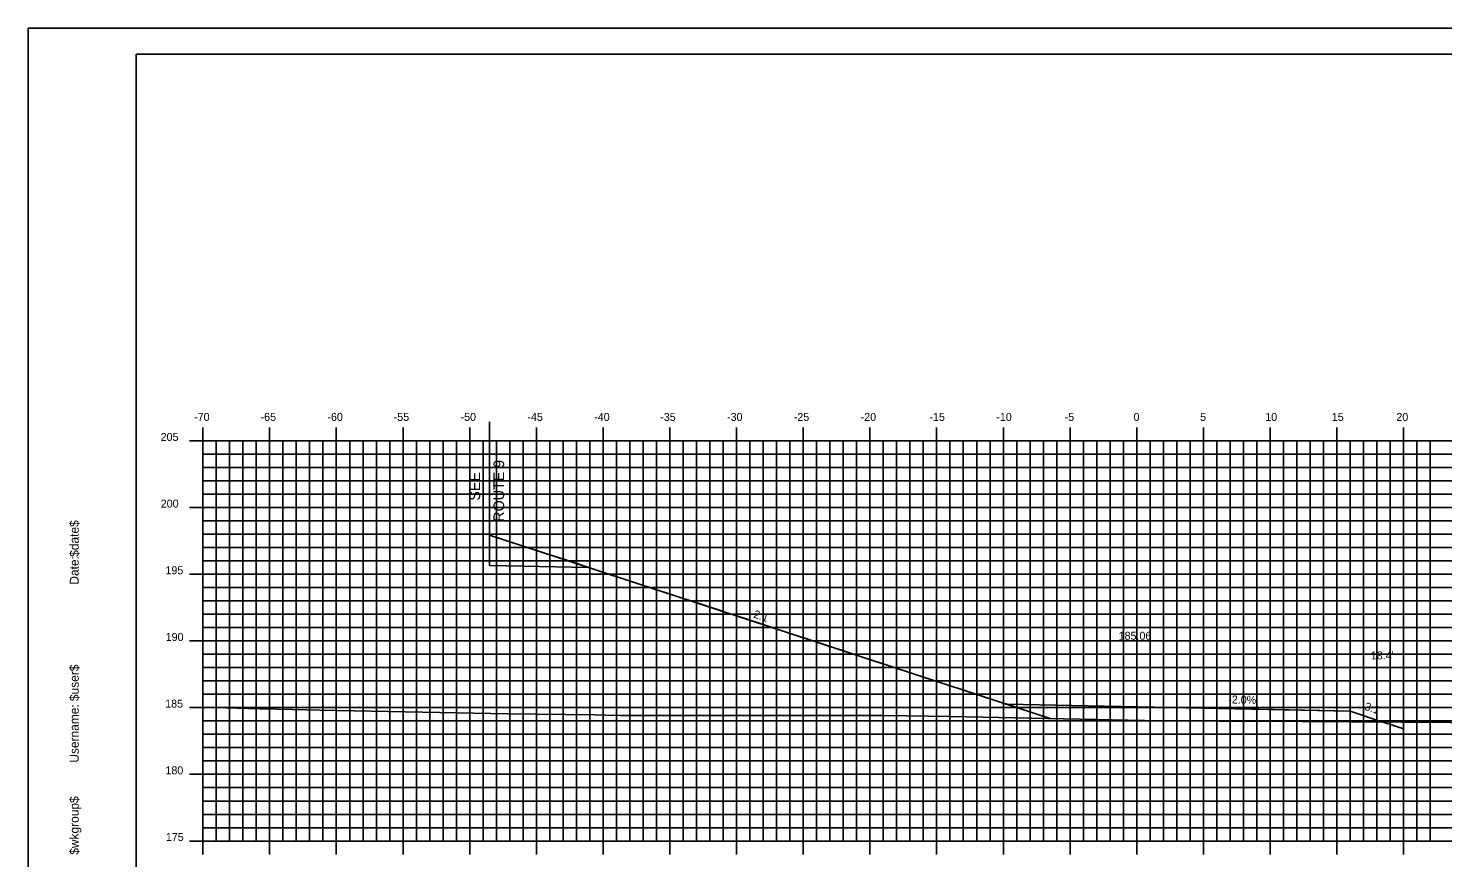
# Model space of a CAD drawing. Extents: x 1724627 to 1724798, y 459560 to 459670.
# Drawn here: x 1724626.6 to 1724732.7, y 459607.4 to 459669.6 of the extents above; entities that cross this region are included whole.
import ezdxf

# ---------------------------------------------------------------- set-up
doc = ezdxf.new("R2010")
doc.units = 0
for name, color, linetype in [('ANNOTATION', 7, 'Continuous'), ('BORDER', 7, 'Continuous'), ('D_Roadway_Centerline', 7, 'Continuous'), ('D_Roadway_Centerline_Text', 7, 'Continuous'), ('D_Roadway_Edge_Shoulder', 7, 'Continuous'), ('D_Roadway_SlopeLines', 7, 'Continuous'), ('D_Roadway_SubGrade', 7, 'Continuous'), ('D_Text_Standard', 7, 'Continuous'), ('H_V ANNOTATION', 7, 'Continuous'), ('MAJOR', 7, 'Continuous'), ('MINOR', 7, 'Continuous'), ('PLOT BOUNDARY', 7, 'Continuous'), ('S_Roadway_Centerline', 7, 'Continuous')]:
    doc.layers.add(name, color=color, linetype=linetype)

msp = doc.modelspace()

# ---------------------------------------------------------------- linework, layer by layer
msp.add_lwpolyline([(1724709.74, 459618.67), (1724717.74, 459618.51), (1724725.74, 459618.35), (1724728.19, 459617.53), (1724728.35, 459617.48), (1724728.49, 459617.43), (1724728.62, 459617.39), (1724728.72, 459617.36), (1724728.93, 459617.29), (1724729.03, 459617.25), (1724729.12, 459617.22), (1724729.2, 459617.2), (1724729.28, 459617.17), (1724729.35, 459617.15), (1724729.41, 459617.13), (1724729.47, 459617.11), (1724729.53, 459617.09), (1724729.58, 459617.07), (1724729.63, 459617.05), (1724729.67, 459617.04)])
at = {"layer": 'BORDER'}
msp.add_lwpolyline([(1724634.74, 459562.61), (1724794.74, 459562.61), (1724794.74, 459667.61), (1724634.74, 459667.61)], close=True, dxfattribs=at)
at = {"layer": 'D_Roadway_Centerline'}
msp.add_lwpolyline([(1724661.23, 459631.55), (1724665.51, 459630.15), (1724666.46, 459629.84), (1724666.86, 459629.71), (1724668.66, 459629.12), (1724670.44, 459628.53), (1724670.57, 459628.49), (1724672.77, 459627.77), (1724673.1, 459627.66), (1724675.37, 459626.92), (1724676.08, 459626.69), (1724678.68, 459625.84), (1724679.17, 459625.68), (1724680.3, 459625.31), (1724681.95, 459624.77), (1724684.59, 459623.9), (1724684.89, 459623.81), (1724685.23, 459623.69), (1724687.98, 459622.79), (1724690.16, 459622.08), (1724690.37, 459622.01), (1724690.5, 459621.97), (1724693.84, 459620.88), (1724695.09, 459620.47), (1724696.14, 459620.12), (1724696.41, 459620.04), (1724699.64, 459618.98), (1724700.02, 459618.86), (1724702.26, 459618.12), (1724702.32, 459618.1), (1724703.24, 459617.8)], dxfattribs=at)
at = {"layer": 'D_Roadway_Edge_Shoulder'}
msp.add_line((1724661.23, 459631.55), (1724661.23, 459631.3), dxfattribs=at)
msp.add_line((1724661.23, 459631.55), (1724661.23, 459631.3), dxfattribs=at)
msp.add_line((1724661.23, 459631.55), (1724661.23, 459631.3), dxfattribs=at)
at = {"layer": 'D_Roadway_SlopeLines'}
for points in [[(1724661.23, 459631.55), (1724703.24, 459617.8)], [(1724725.74, 459618.35), (1724728.19, 459617.53)]]:
    msp.add_lwpolyline(points, dxfattribs=at)
at = {"layer": 'D_Roadway_SubGrade'}
for p, q in [((1724661.23, 459640.05), (1724661.23, 459629.27)), ((1724709.74, 459618.67), (1724699.99, 459618.86))]:
    msp.add_line(p, q, dxfattribs=at)
for points in [[(1724661.23, 459631.3), (1724661.23, 459631.55), (1724668.66, 459629.12), (1724661.23, 459629.27)], [(1724661.23, 459631.3), (1724661.23, 459631.55), (1724668.66, 459629.12), (1724661.23, 459629.27)], [(1724709.74, 459618.67), (1724725.74, 459618.35), (1724728.19, 459617.53)]]:
    msp.add_lwpolyline(points, dxfattribs=at)
at = {"layer": 'MAJOR'}
for p, q in [((1724639.74, 459639.61), (1724639.74, 459638.61)), ((1724644.74, 459639.61), (1724644.74, 459638.61)), ((1724649.74, 459639.61), (1724649.74, 459638.61)), ((1724654.74, 459639.61), (1724654.74, 459638.61)), ((1724659.74, 459639.61), (1724659.74, 459638.61)), ((1724664.74, 459639.61), (1724664.74, 459638.61)), ((1724669.74, 459639.61), (1724669.74, 459638.61)), ((1724674.74, 459639.61), (1724674.74, 459638.61)), ((1724679.74, 459639.61), (1724679.74, 459638.61)), ((1724684.74, 459639.61), (1724684.74, 459638.61)), ((1724689.74, 459639.61), (1724689.74, 459638.61)), ((1724694.74, 459639.61), (1724694.74, 459638.61)), ((1724699.74, 459639.61), (1724699.74, 459638.61)), ((1724704.74, 459639.61), (1724704.74, 459638.61)), ((1724709.74, 459639.61), (1724709.74, 459638.61)), ((1724714.74, 459639.61), (1724714.74, 459638.61)), ((1724719.74, 459639.61), (1724719.74, 459638.61)), ((1724724.74, 459639.61), (1724724.74, 459638.61)), ((1724729.74, 459639.61), (1724729.74, 459638.61)), ((1724638.74, 459638.61), (1724639.74, 459638.61)), ((1724639.74, 459638.61), (1724779.74, 459638.61)), ((1724639.74, 459608.61), (1724639.74, 459638.61)), ((1724639.74, 459608.61), (1724639.74, 459638.61)), ((1724639.74, 459638.61), (1724779.74, 459638.61)), ((1724644.74, 459608.61), (1724644.74, 459638.61)), ((1724649.74, 459608.61), (1724649.74, 459638.61)), ((1724654.74, 459608.61), (1724654.74, 459638.61)), ((1724659.74, 459608.61), (1724659.74, 459638.61)), ((1724664.74, 459608.61), (1724664.74, 459638.61)), ((1724669.74, 459608.61), (1724669.74, 459638.61)), ((1724674.74, 459608.61), (1724674.74, 459638.61)), ((1724679.74, 459608.61), (1724679.74, 459638.61)), ((1724684.74, 459608.61), (1724684.74, 459638.61)), ((1724689.74, 459608.61), (1724689.74, 459638.61)), ((1724694.74, 459608.61), (1724694.74, 459638.61)), ((1724699.74, 459608.61), (1724699.74, 459638.61)), ((1724704.74, 459608.61), (1724704.74, 459638.61)), ((1724709.74, 459608.61), (1724709.74, 459638.61)), ((1724714.74, 459608.61), (1724714.74, 459638.61)), ((1724719.74, 459608.61), (1724719.74, 459638.61)), ((1724724.74, 459608.61), (1724724.74, 459638.61)), ((1724729.74, 459608.61), (1724729.74, 459638.61)), ((1724638.74, 459633.61), (1724639.74, 459633.61)), ((1724639.74, 459633.61), (1724779.74, 459633.61)), ((1724638.74, 459628.61), (1724639.74, 459628.61)), ((1724639.74, 459628.61), (1724779.74, 459628.61)), ((1724638.74, 459623.61), (1724639.74, 459623.61)), ((1724639.74, 459623.61), (1724779.74, 459623.61)), ((1724638.74, 459618.61), (1724639.74, 459618.61)), ((1724639.74, 459618.61), (1724779.74, 459618.61)), ((1724638.74, 459613.61), (1724639.74, 459613.61)), ((1724639.74, 459613.61), (1724779.74, 459613.61)), ((1724638.74, 459608.61), (1724639.74, 459608.61)), ((1724639.74, 459608.61), (1724779.74, 459608.61)), ((1724639.74, 459608.61), (1724779.74, 459608.61)), ((1724639.74, 459607.61), (1724639.74, 459608.61)), ((1724644.74, 459607.61), (1724644.74, 459608.61)), ((1724649.74, 459607.61), (1724649.74, 459608.61)), ((1724654.74, 459607.61), (1724654.74, 459608.61)), ((1724659.74, 459607.61), (1724659.74, 459608.61)), ((1724664.74, 459607.61), (1724664.74, 459608.61)), ((1724669.74, 459607.61), (1724669.74, 459608.61)), ((1724674.74, 459607.61), (1724674.74, 459608.61)), ((1724679.74, 459607.61), (1724679.74, 459608.61)), ((1724684.74, 459607.61), (1724684.74, 459608.61)), ((1724689.74, 459607.61), (1724689.74, 459608.61)), ((1724694.74, 459607.61), (1724694.74, 459608.61)), ((1724699.74, 459607.61), (1724699.74, 459608.61)), ((1724704.74, 459607.61), (1724704.74, 459608.61)), ((1724709.74, 459607.61), (1724709.74, 459608.61)), ((1724714.74, 459607.61), (1724714.74, 459608.61)), ((1724719.74, 459607.61), (1724719.74, 459608.61)), ((1724724.74, 459607.61), (1724724.74, 459608.61)), ((1724729.74, 459607.61), (1724729.74, 459608.61))]:
    msp.add_line(p, q, dxfattribs=at)
at = {"layer": 'MINOR'}
for p, q in [((1724640.74, 459608.61), (1724640.74, 459638.61)), ((1724641.74, 459608.61), (1724641.74, 459638.61)), ((1724642.74, 459608.61), (1724642.74, 459638.61)), ((1724643.74, 459608.61), (1724643.74, 459638.61)), ((1724645.74, 459608.61), (1724645.74, 459638.61)), ((1724646.74, 459608.61), (1724646.74, 459638.61)), ((1724647.74, 459608.61), (1724647.74, 459638.61)), ((1724648.74, 459608.61), (1724648.74, 459638.61)), ((1724650.74, 459608.61), (1724650.74, 459638.61)), ((1724651.74, 459608.61), (1724651.74, 459638.61)), ((1724652.74, 459608.61), (1724652.74, 459638.61)), ((1724653.74, 459608.61), (1724653.74, 459638.61)), ((1724655.74, 459608.61), (1724655.74, 459638.61)), ((1724656.74, 459608.61), (1724656.74, 459638.61)), ((1724657.74, 459608.61), (1724657.74, 459638.61)), ((1724658.74, 459608.61), (1724658.74, 459638.61)), ((1724660.74, 459608.61), (1724660.74, 459638.61)), ((1724661.74, 459608.61), (1724661.74, 459638.61)), ((1724662.74, 459608.61), (1724662.74, 459638.61)), ((1724663.74, 459608.61), (1724663.74, 459638.61)), ((1724665.74, 459608.61), (1724665.74, 459638.61)), ((1724666.74, 459608.61), (1724666.74, 459638.61)), ((1724667.74, 459608.61), (1724667.74, 459638.61)), ((1724668.74, 459608.61), (1724668.74, 459638.61)), ((1724670.74, 459608.61), (1724670.74, 459638.61)), ((1724671.74, 459608.61), (1724671.74, 459638.61)), ((1724672.74, 459608.61), (1724672.74, 459638.61)), ((1724673.74, 459608.61), (1724673.74, 459638.61)), ((1724675.74, 459608.61), (1724675.74, 459638.61)), ((1724676.74, 459608.61), (1724676.74, 459638.61)), ((1724677.74, 459608.61), (1724677.74, 459638.61)), ((1724678.74, 459608.61), (1724678.74, 459638.61)), ((1724680.74, 459608.61), (1724680.74, 459638.61)), ((1724681.74, 459608.61), (1724681.74, 459638.61)), ((1724682.74, 459608.61), (1724682.74, 459638.61)), ((1724683.74, 459608.61), (1724683.74, 459638.61)), ((1724685.74, 459608.61), (1724685.74, 459638.61)), ((1724686.74, 459608.61), (1724686.74, 459638.61)), ((1724687.74, 459608.61), (1724687.74, 459638.61)), ((1724688.74, 459608.61), (1724688.74, 459638.61)), ((1724690.74, 459608.61), (1724690.74, 459638.61)), ((1724691.74, 459608.61), (1724691.74, 459638.61)), ((1724692.74, 459608.61), (1724692.74, 459638.61)), ((1724693.74, 459608.61), (1724693.74, 459638.61)), ((1724695.74, 459608.61), (1724695.74, 459638.61)), ((1724696.74, 459608.61), (1724696.74, 459638.61)), ((1724697.74, 459608.61), (1724697.74, 459638.61)), ((1724698.74, 459608.61), (1724698.74, 459638.61)), ((1724700.74, 459608.61), (1724700.74, 459638.61)), ((1724701.74, 459608.61), (1724701.74, 459638.61)), ((1724702.74, 459608.61), (1724702.74, 459638.61)), ((1724703.74, 459608.61), (1724703.74, 459638.61)), ((1724705.74, 459608.61), (1724705.74, 459638.61)), ((1724706.74, 459608.61), (1724706.74, 459638.61)), ((1724707.74, 459608.61), (1724707.74, 459638.61)), ((1724708.74, 459608.61), (1724708.74, 459638.61)), ((1724710.74, 459608.61), (1724710.74, 459638.61)), ((1724711.74, 459608.61), (1724711.74, 459638.61)), ((1724712.74, 459608.61), (1724712.74, 459638.61)), ((1724713.74, 459608.61), (1724713.74, 459638.61)), ((1724715.74, 459608.61), (1724715.74, 459638.61)), ((1724716.74, 459608.61), (1724716.74, 459638.61)), ((1724717.74, 459608.61), (1724717.74, 459638.61)), ((1724718.74, 459608.61), (1724718.74, 459638.61)), ((1724720.74, 459608.61), (1724720.74, 459638.61)), ((1724721.74, 459608.61), (1724721.74, 459638.61)), ((1724722.74, 459608.61), (1724722.74, 459638.61)), ((1724723.74, 459608.61), (1724723.74, 459638.61)), ((1724725.74, 459608.61), (1724725.74, 459638.61)), ((1724726.74, 459608.61), (1724726.74, 459638.61)), ((1724727.74, 459608.61), (1724727.74, 459638.61)), ((1724728.74, 459608.61), (1724728.74, 459638.61)), ((1724730.74, 459608.61), (1724730.74, 459638.61)), ((1724731.74, 459608.61), (1724731.74, 459638.61)), ((1724639.74, 459637.61), (1724779.74, 459637.61)), ((1724639.74, 459637.61), (1724640.74, 459637.61)), ((1724639.74, 459636.61), (1724779.74, 459636.61)), ((1724639.74, 459636.61), (1724640.74, 459636.61)), ((1724639.74, 459635.61), (1724779.74, 459635.61)), ((1724639.74, 459635.61), (1724640.74, 459635.61)), ((1724639.74, 459634.61), (1724779.74, 459634.61)), ((1724639.74, 459634.61), (1724640.74, 459634.61)), ((1724639.74, 459632.61), (1724779.74, 459632.61)), ((1724639.74, 459632.61), (1724640.74, 459632.61)), ((1724639.74, 459631.61), (1724779.74, 459631.61)), ((1724639.74, 459631.61), (1724640.74, 459631.61)), ((1724639.74, 459630.61), (1724779.74, 459630.61)), ((1724639.74, 459630.61), (1724640.74, 459630.61)), ((1724639.74, 459629.61), (1724779.74, 459629.61)), ((1724639.74, 459629.61), (1724640.74, 459629.61)), ((1724639.74, 459627.61), (1724779.74, 459627.61)), ((1724639.74, 459627.61), (1724640.74, 459627.61)), ((1724639.74, 459626.61), (1724779.74, 459626.61)), ((1724639.74, 459626.61), (1724640.74, 459626.61)), ((1724639.74, 459625.61), (1724779.74, 459625.61)), ((1724639.74, 459625.61), (1724640.74, 459625.61)), ((1724639.74, 459624.61), (1724779.74, 459624.61)), ((1724639.74, 459624.61), (1724640.74, 459624.61)), ((1724639.74, 459622.61), (1724779.74, 459622.61)), ((1724639.74, 459622.61), (1724640.74, 459622.61)), ((1724639.74, 459621.61), (1724779.74, 459621.61)), ((1724639.74, 459621.61), (1724640.74, 459621.61)), ((1724639.74, 459620.61), (1724779.74, 459620.61)), ((1724639.74, 459620.61), (1724640.74, 459620.61)), ((1724639.74, 459619.61), (1724779.74, 459619.61)), ((1724639.74, 459619.61), (1724640.74, 459619.61)), ((1724639.74, 459617.61), (1724779.74, 459617.61)), ((1724639.74, 459617.61), (1724640.74, 459617.61)), ((1724639.74, 459616.61), (1724779.74, 459616.61)), ((1724639.74, 459616.61), (1724640.74, 459616.61)), ((1724639.74, 459615.61), (1724779.74, 459615.61)), ((1724639.74, 459615.61), (1724640.74, 459615.61)), ((1724639.74, 459614.61), (1724779.74, 459614.61)), ((1724639.74, 459614.61), (1724640.74, 459614.61)), ((1724639.74, 459612.61), (1724779.74, 459612.61)), ((1724639.74, 459612.61), (1724640.74, 459612.61)), ((1724639.74, 459611.61), (1724779.74, 459611.61)), ((1724639.74, 459611.61), (1724640.74, 459611.61)), ((1724639.74, 459610.61), (1724779.74, 459610.61)), ((1724639.74, 459610.61), (1724640.74, 459610.61)), ((1724639.74, 459609.61), (1724779.74, 459609.61)), ((1724639.74, 459609.61), (1724640.74, 459609.61))]:
    msp.add_line(p, q, dxfattribs=at)
at = {"layer": 'PLOT BOUNDARY'}
msp.add_lwpolyline([(1724626.65, 459559.55), (1724796.65, 459559.55), (1724796.65, 459669.55), (1724626.65, 459669.55)], close=True, dxfattribs=at)
at = {"layer": 'S_Roadway_Centerline'}
msp.add_lwpolyline([(1724639.74, 459618.64), (1724644.02, 459618.51), (1724646.46, 459618.47), (1724648.51, 459618.41), (1724662.6, 459618.15), (1724669.11, 459618.06), (1724669.94, 459618.04), (1724671.04, 459618.02), (1724690.81, 459618.02), (1724695.78, 459617.95), (1724711.52, 459617.63), (1724715.92, 459617.59), (1724722.15, 459617.58), (1724733.25, 459617.49), (1724739.57, 459617.39), (1724753.07, 459617.44), (1724763.02, 459617.29), (1724775.34, 459617.02), (1724775.49, 459617.02), (1724775.59, 459617.02), (1724776.61, 459616.98), (1724779.74, 459616.89)], dxfattribs=at)

# ---------------------------------------------------------------- texts
at = {"layer": 'ANNOTATION'}
for s, height, rotation, p in [('ROUTE 9', 0.8, 90, (1724662.32, 459632.55)), ('SEE', 0.8, 90, (1724660.52, 459634.13)), ('2:1', 0.6, 341.5651, (1724680.96, 459625.38)), ('-2.0%', 0.6, 358.8542, (1724716.59, 459618.93)), ('3:1', 0.6, 341.5651, (1724726.77, 459618.46))]:
    msp.add_text(s, height=height, rotation=rotation, dxfattribs=at).set_placement(p)
at = {"layer": 'BORDER'}
for s, p in [('$date$', (1724630.43, 459629.92)), ('Date:', (1724630.43, 459627.83)), ('$user$', (1724630.43, 459619.1)), ('Username:', (1724630.43, 459614.48)), ('$wkgroup$', (1724630.43, 459607.58))]:
    msp.add_text(s, height=0.67, rotation=90, dxfattribs=at).set_placement(p)
at = {"layer": 'D_Roadway_Centerline_Text'}
msp.add_text('185.06', height=0.6, dxfattribs=at).set_placement((1724708.38, 459623.7))
at = {"layer": 'D_Text_Standard'}
msp.add_text("18.4'", height=0.6, dxfattribs=at).set_placement((1724727.28, 459622.23))
at = {"layer": 'H_V ANNOTATION'}
for s, p in [('-70', (1724639.08, 459640.11)), ('-65', (1724644.06, 459640.11)), ('-60', (1724649.07, 459640.11)), ('-55', (1724654.04, 459640.11)), ('-50', (1724659.05, 459640.11)), ('-45', (1724664.06, 459640.11)), ('-40', (1724669.07, 459640.11)), ('-35', (1724674.02, 459640.11)), ('-30', (1724679.03, 459640.11)), ('-25', (1724684.03, 459640.11)), ('-20', (1724689.04, 459640.11)), ('-15', (1724694.2, 459640.11)), ('-10', (1724699.21, 459640.11)), ('-5', (1724704.33, 459640.11)), ('0', (1724709.5, 459640.11)), ('5', (1724714.49, 459640.11)), ('10', (1724719.37, 459640.11)), ('15', (1724724.36, 459640.11)), ('20', (1724729.2, 459640.11)), ('205', (1724636.57, 459638.61)), ('200', (1724636.58, 459633.61)), ('195', (1724636.93, 459628.61)), ('190', (1724636.95, 459623.61)), ('185', (1724636.91, 459618.61)), ('180', (1724636.93, 459613.61)), ('175', (1724636.96, 459608.61))]:
    msp.add_text(s, height=0.6, dxfattribs=at).set_placement(p)
at = {"layer": 'MAJOR'}
msp.add_text('-', height=0.006, dxfattribs=at).set_placement((1724639.74, 459608.61))

doc.saveas('drawing.dxf')
